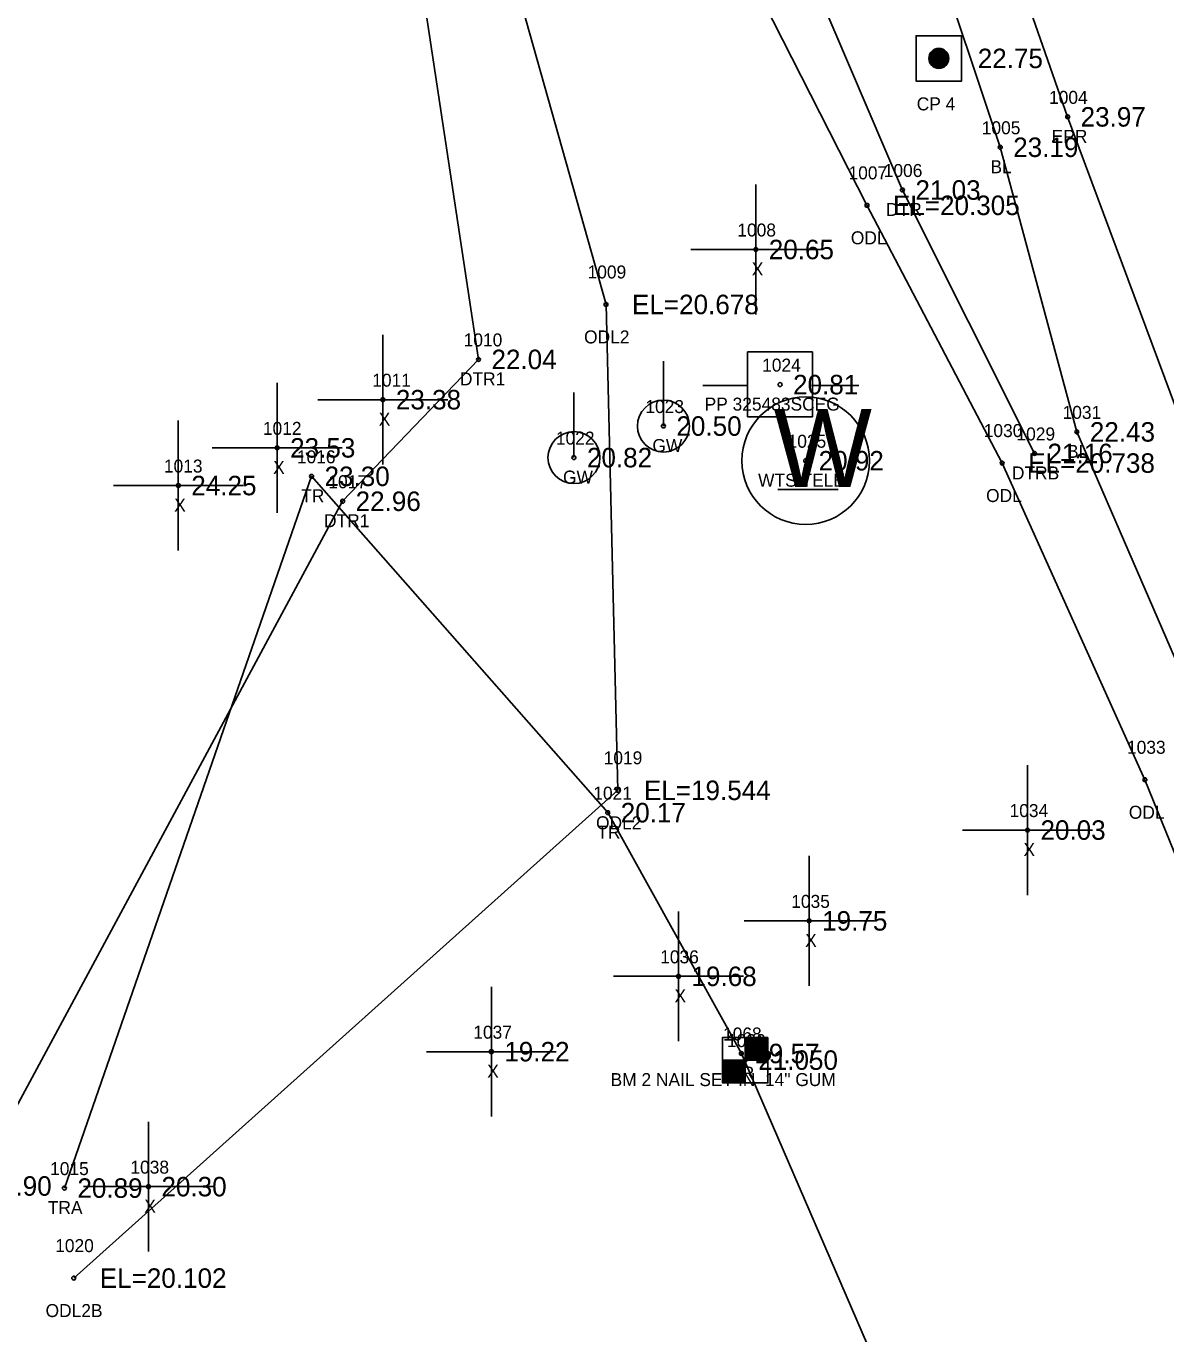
# Model space of a CAD drawing. Extents: x 2042211 to 2045853, y 303080 to 309569.
# Drawn here: x 2042861.3 to 2042949.1, y 306601.3 to 306702 of the extents above; entities that cross this region are included whole.
import ezdxf

# ---------------------------------------------------------------- set-up
doc = ezdxf.new("R2010")
doc.units = 0
for name, color, linetype in [('BR_500YR_SCOUR', 7, 'Continuous'), ('RD_DTM_BkLn1', 7, 'Continuous'), ('RD_DTM_BkLn_txCode', 7, 'Continuous'), ('RD_EX_H2O', 7, 'Continuous'), ('RD_EX_H2O_txCode', 7, 'Continuous'), ('RD_EX_Misc', 7, 'Continuous'), ('RD_EX_Misc_txCode', 7, 'Continuous'), ('RD_EX_Road', 7, 'Continuous'), ('RD_EX_Road_txCode', 7, 'Continuous'), ('RD_EX_TX_H2O_ELEV', 7, 'Continuous'), ('RD_EX_TX_Misc_ELEV', 7, 'Continuous'), ('RD_EX_TX_Road_ELEV', 7, 'Continuous'), ('RD_EX_TX_UT_ELEV', 7, 'Continuous'), ('RD_EX_TX_VEG_ELEV', 7, 'Continuous'), ('RD_EX_UT_txCode', 7, 'Continuous'), ('RD_EX_VEG_txCode', 7, 'Continuous'), ('RD_HC_Survey_ELEV', 7, 'Continuous'), ('RD_HC_Survey_txCode', 7, 'Continuous'), ('RD_SMD_Locator', 7, 'Continuous')]:
    doc.layers.add(name, color=color, linetype=linetype)

msp = doc.modelspace()

# ---------------------------------------------------------------- linework, layer by layer
at = {"layer": 'BR_500YR_SCOUR'}
for p, q in [((2042930.92, 306699.11), (2042930.92, 306699.93)), ((2042930.95, 306699.07), (2042930.95, 306699.97)), ((2042930.97, 306699.04), (2042930.97, 306700)), ((2042931, 306699.01), (2042931, 306700.03)), ((2042931.02, 306698.98), (2042931.02, 306700.06)), ((2042931.05, 306698.96), (2042931.05, 306700.08)), ((2042931.07, 306698.94), (2042931.07, 306700.1)), ((2042931.1, 306698.92), (2042931.1, 306700.12)), ((2042931.12, 306698.9), (2042931.12, 306700.14)), ((2042931.15, 306698.88), (2042931.15, 306700.16)), ((2042931.17, 306698.86), (2042931.17, 306700.18)), ((2042931.2, 306698.85), (2042931.2, 306700.19)), ((2042931.22, 306698.84), (2042931.22, 306700.2)), ((2042931.25, 306698.82), (2042931.25, 306700.22)), ((2042931.27, 306698.81), (2042931.27, 306700.23)), ((2042931.29, 306698.8), (2042931.29, 306700.24)), ((2042931.32, 306698.79), (2042931.32, 306700.25)), ((2042931.34, 306698.79), (2042931.34, 306700.25)), ((2042931.37, 306698.78), (2042931.37, 306700.26)), ((2042931.39, 306698.77), (2042931.39, 306700.27)), ((2042931.42, 306698.77), (2042931.42, 306700.27)), ((2042931.44, 306698.76), (2042931.44, 306700.28)), ((2042931.47, 306698.76), (2042931.47, 306700.28)), ((2042931.49, 306698.75), (2042931.49, 306700.29)), ((2042931.52, 306698.75), (2042931.52, 306700.29)), ((2042931.54, 306698.75), (2042931.54, 306700.29)), ((2042931.57, 306698.75), (2042931.57, 306700.29)), ((2042931.59, 306698.75), (2042931.59, 306700.29)), ((2042931.62, 306698.75), (2042931.62, 306700.29)), ((2042931.64, 306698.75), (2042931.64, 306700.29)), ((2042931.67, 306698.76), (2042931.67, 306700.28)), ((2042931.69, 306698.76), (2042931.69, 306700.28)), ((2042931.72, 306698.76), (2042931.72, 306700.28)), ((2042931.74, 306698.77), (2042931.74, 306700.27)), ((2042931.77, 306698.78), (2042931.77, 306700.27)), ((2042931.79, 306698.78), (2042931.79, 306700.26)), ((2042931.81, 306698.79), (2042931.81, 306700.25)), ((2042931.84, 306698.8), (2042931.84, 306700.24)), ((2042931.86, 306698.81), (2042931.86, 306700.23)), ((2042931.89, 306698.82), (2042931.89, 306700.22)), ((2042931.91, 306698.83), (2042931.91, 306700.21)), ((2042931.94, 306698.84), (2042931.94, 306700.2)), ((2042931.96, 306698.86), (2042931.96, 306700.18)), ((2042931.99, 306698.87), (2042931.99, 306700.17)), ((2042932.01, 306698.89), (2042932.01, 306700.15)), ((2042932.04, 306698.91), (2042932.04, 306700.13)), ((2042932.06, 306698.93), (2042932.06, 306700.11)), ((2042932.09, 306698.95), (2042932.09, 306700.09)), ((2042932.11, 306698.97), (2042932.11, 306700.07)), ((2042932.14, 306699), (2042932.14, 306700.04)), ((2042932.16, 306699.02), (2042932.16, 306700.02)), ((2042932.19, 306699.05), (2042932.19, 306699.99)), ((2042932.21, 306699.09), (2042932.21, 306699.95)), ((2042932.24, 306699.13), (2042932.24, 306699.91)), ((2042930.82, 306699.34), (2042930.82, 306699.7)), ((2042930.85, 306699.26), (2042930.85, 306699.78)), ((2042930.87, 306699.2), (2042930.87, 306699.84)), ((2042930.9, 306699.15), (2042930.9, 306699.89)), ((2042932.26, 306699.17), (2042932.26, 306699.87)), ((2042932.28, 306699.23), (2042932.28, 306699.81)), ((2042932.31, 306699.3), (2042932.31, 306699.74)), ((2042932.33, 306699.41), (2042932.33, 306699.63)), ((2042921.84, 306676.92), (2042916.84, 306676.92)), ((2042916.84, 306676.92), (2042916.84, 306671.92)), ((2042921.84, 306671.92), (2042921.84, 306676.92)), ((2042910.37, 306671.22), (2042910.37, 306676.22)), ((2042903.48, 306668.79), (2042903.48, 306673.79)), ((2042913.41, 306674.35), (2042916.88, 306674.35)), ((2042921.77, 306674.35), (2042925.41, 306674.35)), ((2042916.84, 306671.92), (2042921.84, 306671.92)), ((2042919.19, 306666.34), (2042923.82, 306666.34)), ((2042916.67, 306624.16), (2042916.67, 306620.66)), ((2042916.69, 306624.16), (2042916.69, 306622.41)), ((2042916.71, 306624.16), (2042916.71, 306622.41)), ((2042916.74, 306624.16), (2042916.74, 306622.41)), ((2042916.76, 306624.16), (2042916.76, 306622.41)), ((2042916.79, 306624.16), (2042916.79, 306622.41)), ((2042916.81, 306624.16), (2042916.81, 306622.41)), ((2042916.84, 306624.16), (2042916.84, 306622.41)), ((2042916.86, 306624.16), (2042916.86, 306622.41)), ((2042916.89, 306624.16), (2042916.89, 306622.41)), ((2042916.91, 306624.16), (2042916.91, 306622.41)), ((2042916.94, 306624.16), (2042916.94, 306622.41)), ((2042916.96, 306624.16), (2042916.96, 306622.41)), ((2042916.99, 306624.16), (2042916.99, 306622.41)), ((2042917.01, 306624.16), (2042917.01, 306622.41)), ((2042917.03, 306624.16), (2042917.03, 306622.41)), ((2042917.06, 306624.16), (2042917.06, 306622.41)), ((2042917.08, 306624.16), (2042917.08, 306622.41)), ((2042917.11, 306624.16), (2042917.11, 306622.41)), ((2042917.13, 306624.16), (2042917.13, 306622.41)), ((2042917.16, 306624.16), (2042917.16, 306622.41)), ((2042917.18, 306624.16), (2042917.18, 306622.41)), ((2042917.21, 306624.16), (2042917.21, 306622.41)), ((2042917.23, 306624.16), (2042917.23, 306622.41)), ((2042917.26, 306624.16), (2042917.26, 306622.41)), ((2042917.28, 306624.16), (2042917.28, 306622.41)), ((2042917.31, 306624.16), (2042917.31, 306622.41)), ((2042917.33, 306624.16), (2042917.33, 306622.41)), ((2042917.36, 306624.16), (2042917.36, 306622.41)), ((2042917.38, 306624.16), (2042917.38, 306622.41)), ((2042917.41, 306624.16), (2042917.41, 306622.41)), ((2042917.43, 306624.16), (2042917.43, 306622.41)), ((2042917.46, 306624.16), (2042917.46, 306622.41)), ((2042917.48, 306624.16), (2042917.48, 306622.41)), ((2042917.5, 306624.16), (2042917.5, 306622.41)), ((2042917.53, 306624.16), (2042917.53, 306622.41)), ((2042917.55, 306624.16), (2042917.55, 306622.41)), ((2042917.58, 306624.16), (2042917.58, 306622.41)), ((2042917.6, 306624.16), (2042917.6, 306622.41)), ((2042917.63, 306624.16), (2042917.63, 306622.41)), ((2042917.65, 306624.16), (2042917.65, 306622.41)), ((2042917.68, 306624.16), (2042917.68, 306622.41)), ((2042917.7, 306624.16), (2042917.7, 306622.41)), ((2042917.73, 306624.16), (2042917.73, 306622.41)), ((2042917.75, 306624.16), (2042917.75, 306622.41)), ((2042917.78, 306624.16), (2042917.78, 306622.41)), ((2042917.8, 306624.16), (2042917.8, 306622.41)), ((2042917.83, 306624.16), (2042917.83, 306622.41)), ((2042917.85, 306624.16), (2042917.85, 306622.41)), ((2042917.88, 306624.16), (2042917.88, 306622.41)), ((2042917.9, 306624.16), (2042917.9, 306622.41)), ((2042917.93, 306624.16), (2042917.93, 306622.41)), ((2042917.95, 306624.16), (2042917.95, 306622.41)), ((2042917.98, 306624.16), (2042917.98, 306622.41)), ((2042918, 306624.16), (2042918, 306622.41)), ((2042918.02, 306624.16), (2042918.02, 306622.41)), ((2042918.05, 306624.16), (2042918.05, 306622.41)), ((2042918.07, 306624.16), (2042918.07, 306622.41)), ((2042918.1, 306624.16), (2042918.1, 306622.41)), ((2042918.12, 306624.16), (2042918.12, 306622.41)), ((2042918.15, 306624.16), (2042918.15, 306622.41)), ((2042918.17, 306624.16), (2042918.17, 306622.41)), ((2042918.2, 306624.16), (2042918.2, 306622.41)), ((2042918.22, 306624.16), (2042918.22, 306622.41)), ((2042918.25, 306624.16), (2042918.25, 306622.41)), ((2042918.27, 306624.16), (2042918.27, 306622.41)), ((2042918.3, 306624.16), (2042918.3, 306622.41)), ((2042918.32, 306624.16), (2042918.32, 306622.41)), ((2042918.35, 306624.16), (2042918.35, 306622.41)), ((2042918.37, 306624.16), (2042918.37, 306622.41)), ((2042918.4, 306624.16), (2042918.4, 306622.41)), ((2042918.42, 306622.41), (2042914.92, 306622.41)), ((2042914.92, 306622.41), (2042914.92, 306620.66)), ((2042914.95, 306622.41), (2042914.95, 306620.66)), ((2042914.97, 306622.41), (2042914.97, 306620.66)), ((2042914.99, 306622.41), (2042914.99, 306620.66)), ((2042915.02, 306622.41), (2042915.02, 306620.66)), ((2042915.04, 306622.41), (2042915.04, 306620.66)), ((2042915.07, 306622.41), (2042915.07, 306620.66)), ((2042915.09, 306622.41), (2042915.09, 306620.66)), ((2042915.12, 306622.41), (2042915.12, 306620.66)), ((2042915.14, 306622.41), (2042915.14, 306620.66)), ((2042915.17, 306622.41), (2042915.17, 306620.66)), ((2042915.19, 306622.41), (2042915.19, 306620.66)), ((2042915.22, 306622.41), (2042915.22, 306620.66)), ((2042915.24, 306622.41), (2042915.24, 306620.66)), ((2042915.27, 306622.41), (2042915.27, 306620.66)), ((2042915.29, 306622.41), (2042915.29, 306620.66)), ((2042915.32, 306622.41), (2042915.32, 306620.66)), ((2042915.34, 306622.41), (2042915.34, 306620.66)), ((2042915.37, 306622.41), (2042915.37, 306620.66)), ((2042915.39, 306622.41), (2042915.39, 306620.66)), ((2042915.42, 306622.41), (2042915.42, 306620.66)), ((2042915.44, 306622.41), (2042915.44, 306620.66)), ((2042915.47, 306622.41), (2042915.47, 306620.66)), ((2042915.49, 306622.41), (2042915.49, 306620.66)), ((2042915.51, 306622.41), (2042915.51, 306620.66)), ((2042915.54, 306622.41), (2042915.54, 306620.66)), ((2042915.56, 306622.41), (2042915.56, 306620.66)), ((2042915.59, 306622.41), (2042915.59, 306620.66)), ((2042915.61, 306622.41), (2042915.61, 306620.66)), ((2042915.64, 306622.41), (2042915.64, 306620.66)), ((2042915.66, 306622.41), (2042915.66, 306620.66)), ((2042915.69, 306622.41), (2042915.69, 306620.66)), ((2042915.71, 306622.41), (2042915.71, 306620.66)), ((2042915.74, 306622.41), (2042915.74, 306620.66)), ((2042915.76, 306622.41), (2042915.76, 306620.66)), ((2042915.79, 306622.41), (2042915.79, 306620.66)), ((2042915.81, 306622.41), (2042915.81, 306620.66)), ((2042915.84, 306622.41), (2042915.84, 306620.66)), ((2042915.86, 306622.41), (2042915.86, 306620.66)), ((2042915.89, 306622.41), (2042915.89, 306620.66)), ((2042915.91, 306622.41), (2042915.91, 306620.66)), ((2042915.94, 306622.41), (2042915.94, 306620.66)), ((2042915.96, 306622.41), (2042915.96, 306620.66)), ((2042915.98, 306622.41), (2042915.98, 306620.66)), ((2042916.01, 306622.41), (2042916.01, 306620.66)), ((2042916.03, 306622.41), (2042916.03, 306620.66)), ((2042916.06, 306622.41), (2042916.06, 306620.66)), ((2042916.08, 306622.41), (2042916.08, 306620.66)), ((2042916.11, 306622.41), (2042916.11, 306620.66)), ((2042916.13, 306622.41), (2042916.13, 306620.66)), ((2042916.16, 306622.41), (2042916.16, 306620.66)), ((2042916.18, 306622.41), (2042916.18, 306620.66)), ((2042916.21, 306622.41), (2042916.21, 306620.66)), ((2042916.23, 306622.41), (2042916.23, 306620.66)), ((2042916.26, 306622.41), (2042916.26, 306620.66)), ((2042916.28, 306622.41), (2042916.28, 306620.66)), ((2042916.31, 306622.41), (2042916.31, 306620.66)), ((2042916.33, 306622.41), (2042916.33, 306620.66)), ((2042916.36, 306622.41), (2042916.36, 306620.66)), ((2042916.38, 306622.41), (2042916.38, 306620.66)), ((2042916.41, 306622.41), (2042916.41, 306620.66)), ((2042916.43, 306622.41), (2042916.43, 306620.66)), ((2042916.46, 306622.41), (2042916.46, 306620.66)), ((2042916.48, 306622.41), (2042916.48, 306620.66)), ((2042916.5, 306622.41), (2042916.5, 306620.66)), ((2042916.53, 306622.41), (2042916.53, 306620.66)), ((2042916.55, 306622.41), (2042916.55, 306620.66)), ((2042916.58, 306622.41), (2042916.58, 306620.66)), ((2042916.6, 306622.41), (2042916.6, 306620.66)), ((2042916.63, 306622.41), (2042916.63, 306620.66)), ((2042916.65, 306622.41), (2042916.65, 306620.66))]:
    msp.add_line(p, q, dxfattribs=at)
for points in [[(2042933.32, 306701.27), (2042929.82, 306701.27), (2042929.82, 306697.77), (2042933.32, 306697.77)], [(2042918.42, 306624.16), (2042914.92, 306624.16), (2042914.92, 306620.66), (2042918.42, 306620.66)]]:
    msp.add_lwpolyline(points, close=True, dxfattribs=at)
msp.add_lwpolyline([(2042864.25, 306612.56), (2042883.28, 306667.35), (2042906.08, 306641.46), (2042916.37, 306622.92), (2042928.46, 306594.97), (2042955.8, 306539.7), (2042967.97, 306505.97)], dxfattribs=at)
for centre, radius in [((2042931.57, 306699.52), 0.769), ((2042931.57, 306699.52), 0.15), ((2042919.35, 306674.41), 0.15), ((2042910.37, 306671.22), 2), ((2042921.32, 306668.55), 4.91), ((2042903.48, 306668.79), 2), ((2042910.37, 306671.22), 0.15), ((2042903.48, 306668.79), 0.15), ((2042921.32, 306668.55), 0.15), ((2042883.28, 306667.35), 0.15), ((2042906.08, 306641.46), 0.15), ((2042916.37, 306622.92), 0.15), ((2042916.67, 306622.41), 0.15), ((2042864.25, 306612.56), 0.15)]:
    msp.add_circle(centre, radius, dxfattribs=at)
at = {"layer": 'RD_DTM_BkLn1'}
msp.add_lwpolyline([(2042839.17, 307095.11), (2042841.19, 307080.52), (2042848.71, 307031.33), (2042857.64, 306982.34), (2042868.25, 306933.78), (2042879.62, 306884.9), (2042891.37, 306836.61), (2042906.05, 306788.56), (2042920.38, 306740.36), (2042936.3, 306692.68), (2042942.2, 306670.77), (2042952.72, 306646.49), (2042972.88, 306600.44), (2042993.94, 306554.96), (2043015.19, 306509.48), (2043037.06, 306464.5), (2043060.22, 306420.45)], dxfattribs=at)
at = {"layer": 'RD_EX_H2O'}
for points in [[(2042809.74, 307126.16), (2042806.56, 307122.63), (2042790.31, 307116.78), (2042788.49, 307114.78), (2042791.89, 307113.57), (2042804.81, 307114.94), (2042810.25, 307075.93), (2042820.25, 307025.92), (2042830.4, 306977.21), (2042843.29, 306928.12), (2042852.91, 306878.24), (2042864.55, 306828.43), (2042879.23, 306781.72), (2042889.45, 306748.73), (2042886.16, 306741.98), (2042888.34, 306727.94), (2042896.13, 306676.35), (2042885.67, 306665.43), (2042857.25, 306612.72)], [(2042809.74, 307126.16), (2042815.01, 307124.31), (2042821.79, 307118.99), (2042825.8, 307110.2), (2042827.88, 307100.21), (2042830.08, 307078.71), (2042836.25, 307029.11), (2042845.48, 306980.04), (2042852.07, 306929.46), (2042864.58, 306881.26), (2042879.31, 306833.06), (2042893.37, 306784.78), (2042908.76, 306736.23), (2042928.77, 306689.39), (2042938.94, 306669.11)], [(2042812.2, 307117.75), (2042817.66, 307076.99), (2042828.97, 307027.39), (2042840.42, 306978.95), (2042848.44, 306929.66), (2042859.84, 306880.36), (2042873.68, 306831.67), (2042888.54, 306783.43), (2042900.59, 306749.27), (2042902.9, 306733.67), (2042926.04, 306688.21), (2042936.45, 306668.37), (2042947.44, 306643.99), (2042966.18, 306597.91), (2042985.34, 306551.14), (2042987.61, 306538.59)], [(2042810.02, 307117.36), (2042813.87, 307076.18), (2042825.65, 307027), (2042835.99, 306978.45), (2042846.19, 306929.27), (2042857.5, 306879.97), (2042870.3, 306830.67), (2042885.37, 306782.68), (2042895.57, 306748.28), (2042892.03, 306740.63), (2042891.66, 306731.27), (2042905.95, 306680.58), (2042906.87, 306643.18), (2042864.97, 306605.63)]]:
    msp.add_lwpolyline(points, dxfattribs=at)
at = {"layer": 'RD_EX_Misc'}
for p, q in [((2042917.48, 306679.81), (2042917.48, 306689.81)), ((2042912.48, 306684.81), (2042922.48, 306684.81)), ((2042888.77, 306668.25), (2042888.77, 306678.25)), ((2042880.63, 306664.54), (2042880.63, 306674.54)), ((2042883.77, 306673.25), (2042893.77, 306673.25)), ((2042873.02, 306661.64), (2042873.02, 306671.64)), ((2042875.63, 306669.54), (2042885.63, 306669.54)), ((2042868.02, 306666.64), (2042878.02, 306666.64)), ((2042938.4, 306635.12), (2042938.4, 306645.12)), ((2042933.4, 306640.12), (2042943.4, 306640.12)), ((2042921.59, 306628.13), (2042921.59, 306638.13)), ((2042911.53, 306623.86), (2042911.53, 306633.86)), ((2042916.59, 306633.13), (2042926.59, 306633.13)), ((2042906.53, 306628.86), (2042916.53, 306628.86)), ((2042897.12, 306618.06), (2042897.12, 306628.06)), ((2042892.12, 306623.06), (2042902.12, 306623.06)), ((2042870.72, 306607.67), (2042870.72, 306617.67)), ((2042865.72, 306612.67), (2042875.72, 306612.67))]:
    msp.add_line(p, q, dxfattribs=at)
at = {"layer": 'RD_EX_Road'}
msp.add_lwpolyline([(2042895.94, 306837.56), (2042909.76, 306789.89), (2042925.08, 306742.02), (2042941.49, 306695.02), (2042958.75, 306648.66), (2042978.01, 306602.25), (2042998.08, 306556.93), (2043019.38, 306511.63), (2043041.84, 306466.86), (2043065.03, 306422.83)], dxfattribs=at)
at = {"layer": 'RD_SMD_Locator'}
for centre in [(2042941.49, 306695.02), (2042936.3, 306692.68), (2042928.77, 306689.39), (2042926.04, 306688.21), (2042917.48, 306684.81), (2042905.95, 306680.58), (2042896.13, 306676.35), (2042888.77, 306673.25), (2042942.2, 306670.77), (2042880.63, 306669.54), (2042938.94, 306669.11), (2042936.45, 306668.37), (2042873.02, 306666.64), (2042885.67, 306665.43), (2042947.44, 306643.99), (2042906.87, 306643.18), (2042938.4, 306640.12), (2042921.59, 306633.13), (2042911.53, 306628.86), (2042897.12, 306623.06), (2042870.72, 306612.67), (2042864.97, 306605.63)]:
    msp.add_circle(centre, 0.15, dxfattribs=at)

# ---------------------------------------------------------------- texts
at = {"layer": 'BR_500YR_SCOUR'}
msp.add_text('W', height=6, dxfattribs=at).set_placement((2042918.85, 306666.54))
at = {"layer": 'RD_DTM_BkLn_txCode'}
for s, p in [('1005', (2042934.88, 306693.68)), ('BL', (2042935.55, 306690.68)), ('1031', (2042941.1, 306671.77)), ('BL', (2042941.44, 306668.77))]:
    msp.add_text(s, height=1, dxfattribs=at).set_placement(p)
at = {"layer": 'RD_EX_H2O_txCode'}
for s, p in [('1007', (2042924.62, 306690.21)), ('1006', (2042927.33, 306690.39)), ('DTR', (2042927.51, 306687.39)), ('ODL', (2042924.8, 306685.21)), ('1009', (2042904.53, 306682.58)), ('1010', (2042894.99, 306677.35)), ('ODL2', (2042904.26, 306677.58)), ('DTR1', (2042894.7, 306674.35)), ('1030', (2042935.03, 306670.37)), ('1029', (2042937.55, 306670.11)), ('DTRB', (2042937.2, 306667.11)), ('1017', (2042884.57, 306666.43)), ('ODL', (2042935.21, 306665.37)), ('DTR1', (2042884.24, 306663.43)), ('1033', (2042946.06, 306645.99)), ('1019', (2042905.77, 306645.18)), ('ODL', (2042946.2, 306640.99)), ('ODL2', (2042905.18, 306640.18)), ('1020', (2042863.54, 306607.63)), ('ODL2B', (2042862.8, 306602.63))]:
    msp.add_text(s, height=1, dxfattribs=at).set_placement(p)
at = {"layer": 'RD_EX_Misc_txCode'}
for s, p in [('1008', (2042916.06, 306685.81)), ('X', (2042917.17, 306682.81)), ('1011', (2042887.95, 306674.25)), ('X', (2042888.45, 306671.25)), ('1012', (2042879.53, 306670.54)), ('1013', (2042871.91, 306667.64)), ('X', (2042880.32, 306667.54)), ('X', (2042872.7, 306664.64)), ('1034', (2042937.02, 306641.12)), ('X', (2042938.09, 306638.12)), ('1035', (2042920.21, 306634.13)), ('X', (2042921.28, 306631.13)), ('1036', (2042910.12, 306629.86)), ('X', (2042911.22, 306626.86)), ('1037', (2042895.73, 306624.06)), ('X', (2042896.8, 306621.06)), ('1038', (2042869.33, 306613.67)), ('X', (2042870.4, 306610.67))]:
    msp.add_text(s, height=1, dxfattribs=at).set_placement(p)
at = {"layer": 'RD_EX_Road_txCode'}
for s, p in [('1004', (2042940.06, 306696.02)), ('EPR', (2042940.26, 306693.02))]:
    msp.add_text(s, height=1, dxfattribs=at).set_placement(p)
at = {"layer": 'RD_EX_TX_H2O_ELEV'}
for s, p in [('21.03', (2042929.77, 306688.64)), ('EL=20.305', (2042928.04, 306687.46)), ('EL=20.678', (2042907.95, 306679.83)), ('22.04', (2042897.13, 306675.6)), ('21.16', (2042939.94, 306668.36)), ('EL=20.738', (2042938.45, 306667.62)), ('22.96', (2042886.67, 306664.68)), ('EL=19.544', (2042908.87, 306642.43)), ('21.90', (2042858.25, 306611.97)), ('EL=20.102', (2042866.97, 306604.88))]:
    msp.add_text(s, height=1.5, dxfattribs=at).set_placement(p)
at = {"layer": 'RD_EX_TX_Misc_ELEV'}
for s, p in [('23.19', (2042937.3, 306691.93)), ('20.65', (2042918.48, 306684.06)), ('23.38', (2042889.77, 306672.5)), ('22.43', (2042943.2, 306670.02)), ('23.53', (2042881.63, 306668.79)), ('24.25', (2042874.02, 306665.89)), ('20.03', (2042939.4, 306639.37)), ('19.75', (2042922.59, 306632.38)), ('19.68', (2042912.53, 306628.11)), ('19.22', (2042898.12, 306622.31)), ('20.30', (2042871.72, 306611.92))]:
    msp.add_text(s, height=1.5, dxfattribs=at).set_placement(p)
at = {"layer": 'RD_EX_TX_Road_ELEV'}
msp.add_text('23.97', height=1.5, dxfattribs=at).set_placement((2042942.49, 306694.27))
at = {"layer": 'RD_EX_TX_UT_ELEV'}
for s, p in [('20.50', (2042911.37, 306670.47)), ('20.82', (2042904.48, 306668.04)), ('20.92', (2042922.32, 306667.8))]:
    msp.add_text(s, height=1.5, dxfattribs=at).set_placement(p)
at = {"layer": 'RD_EX_TX_VEG_ELEV'}
for s, p in [('23.30', (2042884.28, 306666.6)), ('20.17', (2042907.08, 306640.71)), ('19.57', (2042917.37, 306622.17)), ('20.89', (2042865.25, 306611.81))]:
    msp.add_text(s, height=1.5, dxfattribs=at).set_placement(p)
at = {"layer": 'RD_EX_UT_txCode'}
for s, p in [('1024', (2042917.97, 306675.41)), ('1023', (2042908.98, 306672.22)), ('PP 325483SCEG', (2042913.54, 306672.41)), ('1022', (2042902.09, 306669.79)), ('GW', (2042909.52, 306669.22)), ('1025', (2042919.93, 306669.55)), ('GW', (2042902.64, 306666.79)), ('WTS TELE', (2042917.66, 306666.55))]:
    msp.add_text(s, height=1, dxfattribs=at).set_placement(p)
at = {"layer": 'RD_EX_VEG_txCode'}
for s, p in [('1016', (2042882.15, 306668.35)), ('TR', (2042882.48, 306665.35)), ('1021', (2042904.97, 306642.46)), ('TR', (2042905.28, 306639.46)), ('1068', (2042914.96, 306623.92)), ('TR', (2042915.58, 306620.92)), ('1015', (2042863.15, 306613.56)), ('TRA', (2042862.97, 306610.56))]:
    msp.add_text(s, height=1, dxfattribs=at).set_placement(p)
at = {"layer": 'RD_HC_Survey_ELEV'}
for s, p in [('22.75', (2042934.57, 306698.77)), ('20.81', (2042920.35, 306673.66)), ('21.050', (2042917.67, 306621.66))]:
    msp.add_text(s, height=1.5, dxfattribs=at).set_placement(p)
at = {"layer": 'RD_HC_Survey_txCode'}
for s, p in [('CP 4', (2042929.87, 306695.52)), ('1026', (2042915.26, 306623.41)), ('BM 2 NAIL SET IN  14" GUM', (2042906.3, 306620.41))]:
    msp.add_text(s, height=1, dxfattribs=at).set_placement(p)

doc.saveas('drawing.dxf')
